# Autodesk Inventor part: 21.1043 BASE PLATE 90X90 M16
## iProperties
Created: 2007-03
Part Number: 21.1043 BASE PLATE 90X90 M16
Document SubType Name: Modeling
Designer: Andy Moles
Material: Aluminum-6061
Mass: 302.507 g
Surface Area: 230.945 cm^2
Volume: 111.626 cm^3
Density: 2.71 g/cm^3
Author: Andy Moles
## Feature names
1. Extrusion1
2. Fillet1
3. Hole1
4. Hole2
5. Hole3
6. Hole4
7. Fillet2
